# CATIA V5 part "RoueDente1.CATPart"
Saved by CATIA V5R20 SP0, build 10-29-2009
Part number: engrenage2
Source: Unknown
Publications: "Esquisse.8", "Plan.3"
Material "Rouge DS": density 7860 kg/m3, Young's modulus 2e+11 Pa, Poisson ratio 0.266
Bounding box of the stored display mesh (mm): x 0 to 10, y -35.499 to 35.499, z -35.499 to 35.499
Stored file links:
  E:\EDELI\gcausse\Edeli_2012_184_gcausse\RoueDente1.CATPart
  C:\usr\gt1\projet\site_web\doc\catia\gears\spur_gear_files\parts\gear_n.CATPart
  C:\Users\thinkmotion1\Desktop\Nouveau dossier\Cremai_Automobile\Cremaillere_automobile.CATProduct
  C:\Program Files\Dassault Systemes\B20\win_b64\startup\materials\French\Catalog.CATMaterial
  C:\Program Files\Dassault Systemes\B20\win_b64\startup\materials\red_env_512x512.jpg
  E:\EDELI\gcausse\Edeli_2012_190_gcausse\Vol3_190.CATProduct
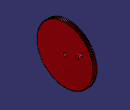
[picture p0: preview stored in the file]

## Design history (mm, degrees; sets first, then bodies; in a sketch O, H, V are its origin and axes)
Parameters
  a = 20 deg
  m = 0.5 mm
  Z = 140
  rp = 35 mm {= m * Z / 2}
  ra = 35.5 mm {= rp + m}
  rb = 32.8892 mm {= rp * cos( a )}
  rf = 34.375 mm {= rp - 1.25 * m}
  rc = 0.19 mm {= m * 0.38}
  c = 0.115855 {= sqrt( 1 / ( cos( a ) * cos( a ) ) - 1 ) / PI}
  phi = 1.4968 deg
  `diametre perçages extérieurs` = 35 mm
Set1
  DatumCurve1: linked copy from another document
Set2
  Line1 "Axe X": stored without definition
  Plane1: type Angle, RefPlane zx-plane, Direction Line1, Angle 1.2857 {= 180deg / Z}
  Point1 "origine": (0, 0, 0)
  Point2: (0, 0, 32.8892)
  Point3: (0, 0.3366, 34.4724)
  Point4: (0, 2.6135, 38.7545)
  Point5: (0, 8.3882, 44.4092)
  Point6: (0, 18.5079, 49.4703)
  Curve1: Elements (Point2; Point3; Point4; Point5; Point6)
  Extrapol1: ToExtrapol Point2, Support Curve1, Length 1 {= m * 2}
  Rotate1: Axis Line1, Angle 1.4968 {= phi}, ToTransfor Extrapol1
  Circle1: type CtrRad, Start 0, End 180, Center Point1, Support yz-plane, Radius 34.375 {= rf}, FirstDirection (0, 1, 0)
  Circle2: type CtrRad, Start 0, End 180, Center Point1, Support yz-plane, Radius 35.5 {= ra}, FirstDirection (0, 1, 0)
  Corner1: Element1 Rotate1, Element2 Circle1, Radius 0.19 {= rc}
  Symmetry1: Reference Plane1, ToTransfor Corner1
  Split1: ToCut Rotate1, Cutting (Corner1; Circle2)
  Symmetry2: Reference zx-plane, ToTransfor Split1
  Circle3: type 2PointsRad, Start 0, End 180, FirstPoint vertex of Symmetry1, SecondPoint vertex of Corner1, Support yz-plane, Radius 34.375 {= rf}
  Circle4: type 2PointsRad, Start 0, End 180, FirstPoint vertex of Split1, SecondPoint vertex of Symmetry2, Support yz-plane, Radius 35.5 {= ra}
  Join1: Elements (Symmetry1; Circle3; Corner1; Split1; Circle4; Symmetry2)
  CircPattern1: of Join1, instances 140 {= Z}, angular step 2.5714 {= 360.0*1 deg/CircPattern1.AngularNumber}, axis from Line1
  Join2: Elements (Join1; CircPattern1)
  Plane2: type Offset, RefPlane yz-plane, Offset 33
  Sketch1 on end face of Pad1, origin (5, 0, 0), H (0, 1, 0), V (0, 0, 1)
    circle A1 centre (0, 0) radius 2.5
    radius A1 = 2.5
Body1 (main body)
  Pad1: profile Join2, length 5
  Sketch2 on Plane2, origin (33, 0, 0), H (0, 1, 0), V (0, 0, 1)
    circle A1 centre (0, 0) radius 31.6677
    radius A1 = 31.6677
  Sketch3 on start face of Pad1, origin (0, 0, 0), H (0, -1, 0), V (0, 0, 1)
    circle A1 centre (0, 0) radius 10
    radius A1 = 10
  Sketch4 on end face of Pad1, origin (5, 0, 0), H (0, 1, 0), V (0, 0, 1)
    circle A1 centre (0, 0) radius 10
    radius A1 = 10
  Pocket1: profile Sketch1, direction (-1, 0, 0), length 5
  Sketch5 on end face of Pad1, origin (5, 0, 0), H (0, 1, 0), V (0, 0, 1)
    circle A1 centre (20, 10) radius 2.5
    radius A1 = 2.5
  Pad2: profile Sketch5, direction (1, 0, 0), length 5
